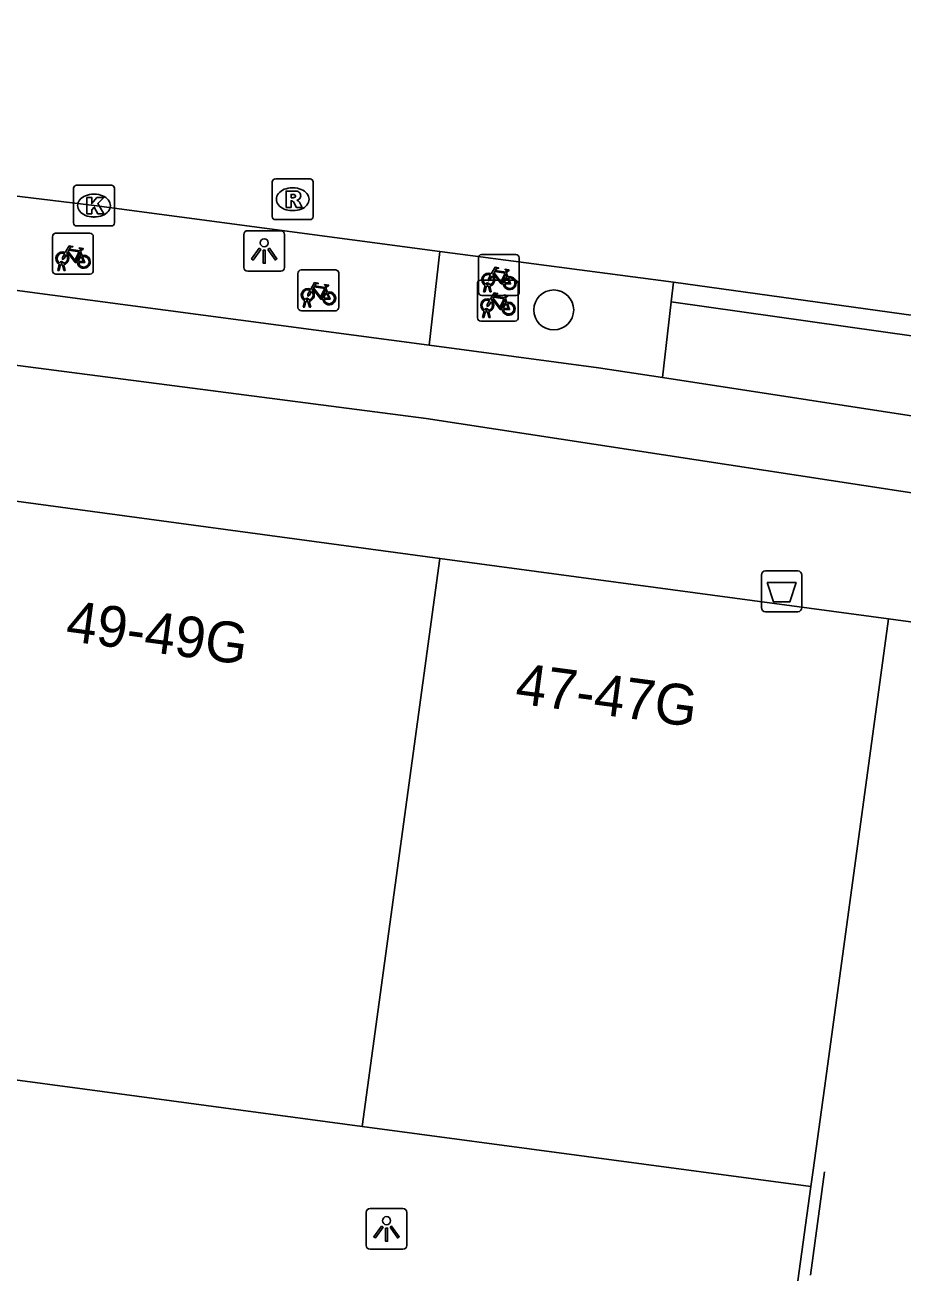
# Model space of a CAD drawing. Extents: x 160664 to 161506, y 382245 to 383288.
# Drawn here: x 160817.07 to 160838.59, y 383245.11 to 383275.84 of the extents above; entities that cross this region are included whole.
import ezdxf

# ---------------------------------------------------------------- set-up
doc = ezdxf.new("R2010")
doc.units = 0
for name, color, linetype in [('IMGEO_Afvalbak', 7, 'Continuous'), ('IMGEO_Berm_open', 7, 'Continuous'), ('IMGEO_Boom', 7, 'Continuous'), ('IMGEO_Fietsenrek', 7, 'Continuous'), ('IMGEO_Fietspad_gesloten', 7, 'Continuous'), ('IMGEO_Kolk', 7, 'Continuous'), ('IMGEO_Lichtpunt', 7, 'Continuous'), ('IMGEO_Muur', 7, 'Continuous'), ('IMGEO_Pand', 7, 'Continuous'), ('IMGEO_Pand_nummerreeks', 7, 'Continuous'), ('IMGEO_Rijbaan_lokaal_gesloten', 7, 'Continuous'), ('IMGEO_Rioolput', 7, 'Continuous'), ('IMGEO_Voetpad_open', 7, 'Continuous')]:
    doc.layers.add(name, color=color, linetype=linetype)

msp = doc.modelspace()

# ---------------------------------------------------------------- linework, layer by layer
at = {"layer": 'IMGEO_Afvalbak'}
for p, q in [((160835.118, 383261.549), (160835.118, 383262.349)), ((160835.118, 383262.349), (160835.118, 383261.549)), ((160835.218, 383262.449), (160836.008, 383262.449)), ((160836.008, 383262.449), (160835.218, 383262.449)), ((160836.108, 383262.349), (160836.108, 383261.549)), ((160836.108, 383261.549), (160836.108, 383262.349)), ((160836.008, 383261.449), (160835.218, 383261.449)), ((160835.218, 383261.449), (160836.008, 383261.449))]:
    msp.add_line(p, q, dxfattribs=at)
msp.add_lwpolyline([(160835.261, 383262.163), (160835.965, 383262.163), (160835.816, 383261.693), (160835.41, 383261.693), (160835.261, 383262.163)], dxfattribs=at)
for centre, start, end in [((160835.218, 383262.349), 90, 180), ((160835.218, 383262.349), 90, 180), ((160836.008, 383262.349), 0, 90), ((160836.008, 383262.349), 360, 90), ((160835.218, 383261.549), 180, 270), ((160835.218, 383261.549), 180, 270), ((160836.008, 383261.549), 270, 0), ((160836.008, 383261.549), 270, 0)]:
    msp.add_arc(centre, 0.1, start, end, dxfattribs=at)
at = {"layer": 'IMGEO_Berm_open'}
for points in [[(160827.23, 383270.288), (160826.971, 383267.984)], [(160832.69, 383267.191), (160832.907, 383269.052)]]:
    msp.add_lwpolyline(points, dxfattribs=at)
at = {"layer": 'IMGEO_Boom'}
msp.add_circle((160830.026, 383268.851), 0.489, dxfattribs=at)
at = {"layer": 'IMGEO_Fietsenrek'}
for p, q in [((160817.739, 383269.806), (160817.739, 383270.647)), ((160817.739, 383270.647), (160817.739, 383269.806)), ((160817.814, 383270.731), (160818.655, 383270.731)), ((160818.655, 383270.731), (160817.814, 383270.731)), ((160818.739, 383270.656), (160818.739, 383269.815)), ((160818.739, 383269.815), (160818.739, 383270.656)), ((160818.426, 383270.28), (160818.462, 383270.185)), ((160828.18, 383269.282), (160828.18, 383270.123)), ((160828.18, 383270.123), (160828.18, 383269.282)), ((160828.255, 383270.207), (160829.096, 383270.207)), ((160829.096, 383270.207), (160828.255, 383270.207)), ((160829.18, 383270.132), (160829.18, 383269.291)), ((160829.18, 383269.291), (160829.18, 383270.132)), ((160818.664, 383269.731), (160817.823, 383269.731)), ((160817.823, 383269.731), (160818.664, 383269.731)), ((160817.866, 383269.815), (160817.905, 383269.975)), ((160817.9, 383269.815), (160817.866, 383269.815)), ((160817.935, 383269.963), (160817.9, 383269.815)), ((160817.977, 383269.987), (160817.976, 383269.991)), ((160818.018, 383269.815), (160817.984, 383269.957)), ((160818.008, 383269.998), (160818.009, 383269.991)), ((160818.016, 383269.961), (160818.051, 383269.815)), ((160818.051, 383269.815), (160818.018, 383269.815)), ((160823.756, 383268.907), (160823.756, 383269.748)), ((160823.756, 383269.748), (160823.756, 383268.907)), ((160823.831, 383269.832), (160824.672, 383269.832)), ((160824.672, 383269.832), (160823.831, 383269.832)), ((160824.756, 383269.757), (160824.756, 383268.916)), ((160824.756, 383268.916), (160824.756, 383269.757)), ((160828.867, 383269.756), (160828.903, 383269.661)), ((160828.155, 383268.654), (160828.155, 383269.495)), ((160828.155, 383269.495), (160828.155, 383268.654)), ((160828.23, 383269.579), (160829.071, 383269.579)), ((160829.071, 383269.579), (160828.23, 383269.579)), ((160828.307, 383269.291), (160828.346, 383269.451)), ((160828.376, 383269.439), (160828.341, 383269.291)), ((160828.418, 383269.463), (160828.417, 383269.467)), ((160828.459, 383269.291), (160828.425, 383269.433)), ((160828.449, 383269.474), (160828.45, 383269.467)), ((160828.457, 383269.437), (160828.492, 383269.291)), ((160829.155, 383269.504), (160829.155, 383268.663)), ((160829.155, 383268.663), (160829.155, 383269.504)), ((160823.994, 383269.088), (160823.993, 383269.092)), ((160824.025, 383269.099), (160824.026, 383269.092)), ((160824.443, 383269.381), (160824.479, 383269.286)), ((160829.105, 383269.207), (160828.264, 383269.207)), ((160828.264, 383269.207), (160829.105, 383269.207)), ((160828.341, 383269.291), (160828.307, 383269.291)), ((160828.492, 383269.291), (160828.459, 383269.291)), ((160828.842, 383269.128), (160828.878, 383269.033)), ((160824.681, 383268.832), (160823.84, 383268.832)), ((160823.84, 383268.832), (160824.681, 383268.832)), ((160823.883, 383268.916), (160823.922, 383269.076)), ((160823.917, 383268.916), (160823.883, 383268.916)), ((160823.952, 383269.064), (160823.917, 383268.916)), ((160824.035, 383268.916), (160824.001, 383269.058)), ((160824.033, 383269.062), (160824.068, 383268.916)), ((160824.068, 383268.916), (160824.035, 383268.916)), ((160828.282, 383268.663), (160828.321, 383268.823)), ((160828.351, 383268.811), (160828.316, 383268.663)), ((160828.393, 383268.835), (160828.392, 383268.839)), ((160828.434, 383268.663), (160828.4, 383268.805)), ((160828.424, 383268.846), (160828.425, 383268.839)), ((160828.432, 383268.809), (160828.467, 383268.663)), ((160829.08, 383268.579), (160828.239, 383268.579)), ((160828.239, 383268.579), (160829.08, 383268.579)), ((160828.316, 383268.663), (160828.282, 383268.663)), ((160828.467, 383268.663), (160828.434, 383268.663))]:
    msp.add_line(p, q, dxfattribs=at)
for points in [[(160818.052, 383270.257), (160818.147, 383270.421), (160818.233, 383270.407), (160818.235, 383270.398), (160818.179, 383270.387), (160818.152, 383270.342), (160818.408, 383270.301)], [(160818.395, 383270.276), (160818.138, 383270.317), (160818.121, 383270.288), (160818.288, 383270.068), (160818.395, 383270.276)], [(160818.408, 383270.301), (160818.433, 383270.35), (160818.427, 383270.354), (160818.404, 383270.358), (160818.392, 383270.365), (160818.391, 383270.368), (160818.393, 383270.373), (160818.488, 383270.358), (160818.49, 383270.348), (160818.48, 383270.335), (160818.468, 383270.329), (160818.454, 383270.335), (160818.426, 383270.28)], [(160818.073, 383270.205), (160818.021, 383270.115), (160817.981, 383270.09), (160817.982, 383270.137), (160818.037, 383270.231)], [(160818.348, 383270.013), (160818.298, 383270.013), (160818.107, 383270.264), (160818.088, 383270.232)], [(160818.443, 383270.178), (160818.413, 383270.255), (160818.304, 383270.037), (160818.347, 383270.037)], [(160818.377, 383270.037), (160818.497, 383270.036), (160818.453, 383270.15)], [(160818.473, 383270.157), (160818.528, 383270.012), (160818.378, 383270.012)], [(160828.514, 383269.681), (160828.462, 383269.591), (160828.422, 383269.566), (160828.423, 383269.613), (160828.478, 383269.707)], [(160828.493, 383269.733), (160828.588, 383269.897), (160828.674, 383269.883), (160828.676, 383269.874), (160828.62, 383269.863), (160828.593, 383269.818), (160828.849, 383269.777)], [(160828.789, 383269.489), (160828.739, 383269.489), (160828.548, 383269.74), (160828.529, 383269.708)], [(160828.836, 383269.752), (160828.579, 383269.793), (160828.562, 383269.764), (160828.729, 383269.544), (160828.836, 383269.752)], [(160828.884, 383269.654), (160828.854, 383269.731), (160828.745, 383269.513), (160828.788, 383269.513)], [(160828.849, 383269.777), (160828.874, 383269.826), (160828.868, 383269.83), (160828.845, 383269.834), (160828.833, 383269.841), (160828.832, 383269.844), (160828.834, 383269.849), (160828.929, 383269.834), (160828.931, 383269.824), (160828.921, 383269.811), (160828.909, 383269.805), (160828.895, 383269.811), (160828.867, 383269.756)], [(160824.069, 383269.358), (160824.164, 383269.522), (160824.25, 383269.508), (160824.252, 383269.499), (160824.196, 383269.488), (160824.169, 383269.443), (160824.425, 383269.402)], [(160824.412, 383269.377), (160824.155, 383269.418), (160824.138, 383269.389), (160824.305, 383269.169), (160824.412, 383269.377)], [(160824.425, 383269.402), (160824.45, 383269.451), (160824.444, 383269.455), (160824.421, 383269.459), (160824.409, 383269.466), (160824.408, 383269.469), (160824.41, 383269.474), (160824.505, 383269.459), (160824.507, 383269.449), (160824.497, 383269.436), (160824.485, 383269.43), (160824.471, 383269.436), (160824.443, 383269.381)], [(160828.818, 383269.513), (160828.938, 383269.512), (160828.894, 383269.626)], [(160828.914, 383269.633), (160828.969, 383269.488), (160828.819, 383269.488)], [(160824.09, 383269.306), (160824.038, 383269.216), (160823.998, 383269.191), (160823.999, 383269.238), (160824.054, 383269.332)], [(160824.365, 383269.114), (160824.315, 383269.114), (160824.124, 383269.365), (160824.105, 383269.333)], [(160824.46, 383269.279), (160824.43, 383269.356), (160824.321, 383269.138), (160824.364, 383269.138)], [(160824.394, 383269.138), (160824.514, 383269.137), (160824.47, 383269.251)], [(160824.49, 383269.258), (160824.545, 383269.113), (160824.395, 383269.113)], [(160828.468, 383269.105), (160828.563, 383269.269), (160828.649, 383269.255), (160828.651, 383269.246), (160828.595, 383269.235), (160828.568, 383269.19), (160828.824, 383269.149)], [(160828.764, 383268.861), (160828.714, 383268.861), (160828.523, 383269.112), (160828.504, 383269.08)], [(160828.811, 383269.124), (160828.554, 383269.165), (160828.537, 383269.136), (160828.704, 383268.916), (160828.811, 383269.124)], [(160828.859, 383269.026), (160828.829, 383269.103), (160828.72, 383268.885), (160828.763, 383268.885)], [(160828.824, 383269.149), (160828.849, 383269.198), (160828.843, 383269.202), (160828.82, 383269.206), (160828.808, 383269.213), (160828.807, 383269.216), (160828.809, 383269.221), (160828.904, 383269.206), (160828.906, 383269.196), (160828.896, 383269.183), (160828.884, 383269.177), (160828.87, 383269.183), (160828.842, 383269.128)], [(160828.489, 383269.053), (160828.437, 383268.963), (160828.397, 383268.938), (160828.398, 383268.985), (160828.453, 383269.079)], [(160828.793, 383268.885), (160828.913, 383268.884), (160828.869, 383268.998)], [(160828.889, 383269.005), (160828.944, 383268.86), (160828.794, 383268.86)]]:
    msp.add_lwpolyline(points, dxfattribs=at)
for centre, radius, start, end in [((160817.817, 383270.653), 0.0779, 92.4484, 184.2845), ((160817.817, 383270.653), 0.0779, 92.4484, 184.2845), ((160818.661, 383270.653), 0.0779, 2.4484, 94.2845), ((160818.661, 383270.653), 0.0779, 2.4484, 94.2845), ((160817.979, 383270.116), 0.159, 62.6766, 242.1369), ((160817.979, 383270.116), 0.129, 63.3192, 238.903), ((160817.959, 383269.987), 0.0499, 12.8025, 158.6934), ((160817.959, 383269.987), 0.0174, 12.8025, 163.4502), ((160817.979, 383270.116), 0.129, 283.6043, 43.4302), ((160817.979, 383270.116), 0.159, 283.5766, 46.6042), ((160818.506, 383270.032), 0.159, 113.3408, 178.3217), ((160818.506, 383270.032), 0.159, 187.0065, 105.7708), ((160818.506, 383270.032), 0.129, 113.923, 177.9556), ((160818.506, 383270.032), 0.129, 188.6715, 104.5883), ((160828.258, 383270.129), 0.0779, 92.4484, 184.2845), ((160828.258, 383270.129), 0.0779, 92.4484, 184.2845), ((160829.102, 383270.129), 0.0779, 2.4484, 94.2845), ((160829.102, 383270.129), 0.0779, 2.4484, 94.2845), ((160817.817, 383269.809), 0.0779, 182.4484, 274.2845), ((160817.817, 383269.809), 0.0779, 182.4484, 274.2845), ((160817.979, 383270.116), 0.159, 253.9967, 271.7867), ((160817.979, 383270.116), 0.129, 253.415, 269.0204), ((160818.661, 383269.809), 0.0779, 272.4484, 4.2845), ((160818.661, 383269.809), 0.0779, 272.4484, 4.2845), ((160823.834, 383269.754), 0.0779, 92.4484, 184.2845), ((160823.834, 383269.754), 0.0779, 92.4484, 184.2845), ((160824.678, 383269.754), 0.0779, 2.4484, 94.2845), ((160824.678, 383269.754), 0.0779, 2.4484, 94.2845), ((160828.42, 383269.592), 0.159, 62.6766, 242.1369), ((160828.42, 383269.592), 0.129, 63.3192, 238.903), ((160828.42, 383269.592), 0.159, 283.5766, 46.6042), ((160828.233, 383269.501), 0.0779, 92.4484, 184.2845), ((160828.233, 383269.501), 0.0779, 92.4484, 184.2845), ((160828.4, 383269.463), 0.0499, 12.8025, 158.6934), ((160828.42, 383269.592), 0.159, 253.9967, 271.7867), ((160828.4, 383269.463), 0.0174, 12.8025, 163.4502), ((160828.42, 383269.592), 0.129, 253.415, 269.0204), ((160828.42, 383269.592), 0.129, 283.6043, 43.4302), ((160828.947, 383269.508), 0.159, 113.3408, 178.3217), ((160828.947, 383269.508), 0.159, 187.0065, 105.7708), ((160828.947, 383269.508), 0.129, 113.923, 177.9556), ((160828.947, 383269.508), 0.129, 188.6715, 104.5883), ((160829.077, 383269.501), 0.0779, 2.4484, 94.2845), ((160829.077, 383269.501), 0.0779, 2.4484, 94.2845), ((160823.996, 383269.217), 0.159, 62.6766, 242.1369), ((160823.996, 383269.217), 0.129, 63.3192, 238.903), ((160823.976, 383269.088), 0.0499, 12.8025, 158.6934), ((160823.976, 383269.088), 0.0174, 12.8025, 163.4502), ((160823.996, 383269.217), 0.129, 253.415, 269.0204), ((160823.996, 383269.217), 0.129, 283.6043, 43.4302), ((160823.996, 383269.217), 0.159, 283.5766, 46.6042), ((160824.523, 383269.133), 0.159, 113.3408, 178.3217), ((160824.523, 383269.133), 0.159, 187.0065, 105.7708), ((160824.523, 383269.133), 0.129, 113.923, 177.9556), ((160824.523, 383269.133), 0.129, 188.6715, 104.5883), ((160828.258, 383269.285), 0.0779, 182.4484, 274.2845), ((160828.258, 383269.285), 0.0779, 182.4484, 274.2845), ((160828.395, 383268.964), 0.159, 62.6766, 242.1369), ((160828.395, 383268.964), 0.129, 63.3192, 238.903), ((160828.395, 383268.964), 0.159, 283.5766, 46.6042), ((160829.102, 383269.285), 0.0779, 272.4484, 4.2845), ((160829.102, 383269.285), 0.0779, 272.4484, 4.2845), ((160823.834, 383268.91), 0.0779, 182.4484, 274.2845), ((160823.834, 383268.91), 0.0779, 182.4484, 274.2845), ((160823.996, 383269.217), 0.159, 253.9967, 271.7867), ((160824.678, 383268.91), 0.0779, 272.4484, 4.2845), ((160824.678, 383268.91), 0.0779, 272.4484, 4.2845), ((160828.375, 383268.835), 0.0499, 12.8025, 158.6934), ((160828.395, 383268.964), 0.159, 253.9967, 271.7867), ((160828.375, 383268.835), 0.0174, 12.8025, 163.4502), ((160828.395, 383268.964), 0.129, 253.415, 269.0204), ((160828.395, 383268.964), 0.129, 283.6043, 43.4302), ((160828.922, 383268.88), 0.159, 113.3408, 178.3217), ((160828.922, 383268.88), 0.159, 187.0065, 105.7708), ((160828.922, 383268.88), 0.129, 113.923, 177.9556), ((160828.922, 383268.88), 0.129, 188.6715, 104.5883), ((160828.233, 383268.657), 0.0779, 182.4484, 274.2845), ((160828.233, 383268.657), 0.0779, 182.4484, 274.2845), ((160829.077, 383268.657), 0.0779, 272.4484, 4.2845), ((160829.077, 383268.657), 0.0779, 272.4484, 4.2845)]:
    msp.add_arc(centre, radius, start, end, dxfattribs=at)
at = {"layer": 'IMGEO_Fietspad_gesloten'}
for points in [[(160749.571, 383275.838), (160772.375, 383273.271), (160826.897, 383266.189), (160865.807, 383260.226)], [(160826.971, 383267.984), (160814.961, 383269.581)], [(160832.69, 383267.191), (160831.127, 383267.431), (160826.971, 383267.984)], [(160850.573, 383264.439), (160832.69, 383267.191)]]:
    msp.add_lwpolyline(points, dxfattribs=at)
at = {"layer": 'IMGEO_Kolk'}
for p, q in [((160818.33, 383271.91), (160819.182, 383271.91)), ((160818.255, 383270.984), (160818.255, 383271.836)), ((160818.743, 383271.69), (160818.768, 383271.69)), ((160819.256, 383271.836), (160819.256, 383270.984)), ((160818.766, 383271.13), (160818.741, 383271.13)), ((160819.182, 383270.91), (160818.33, 383270.91))]:
    msp.add_line(p, q, dxfattribs=at)
for points in [[(160818.33, 383271.91), (160819.182, 383271.91)], [(160818.255, 383270.984), (160818.255, 383271.836)], [(160818.576, 383271.61), (160818.699, 383271.61), (160818.699, 383271.459), (160818.829, 383271.61), (160818.993, 383271.61), (160818.847, 383271.459), (160819, 383271.21), (160818.848, 383271.21), (160818.763, 383271.374), (160818.699, 383271.307), (160818.699, 383271.21), (160818.576, 383271.21), (160818.576, 383271.61)], [(160819.256, 383271.836), (160819.256, 383270.984)], [(160819.182, 383270.91), (160818.33, 383270.91)]]:
    msp.add_lwpolyline(points, dxfattribs=at)
for centre, start, end in [((160818.332, 383271.834), 91.552, 178.448), ((160818.332, 383271.834), 91.552, 178.448), ((160819.18, 383271.834), 1.552, 88.448), ((160819.18, 383271.834), 1.552, 88.448), ((160818.332, 383270.986), 181.552, 268.448), ((160818.332, 383270.986), 181.552, 268.448), ((160819.18, 383270.986), 271.552, 358.448), ((160819.18, 383270.986), 271.552, 358.448)]:
    msp.add_arc(centre, 0.0765, start, end, dxfattribs=at)
for centre, major_axis, ratio, start_param, end_param in [((160818.742, 383271.41), (-0.387, 0.002), 0.722429, 4.712389, 7.853982), ((160818.767, 383271.41), (-0.39, 0.002), 0.717154, 1.570796, 4.712389)]:
    msp.add_ellipse(centre, major_axis=major_axis, ratio=ratio, start_param=start_param, end_param=end_param, dxfattribs=at)
at = {"layer": 'IMGEO_Lichtpunt'}
for p, q in [((160822.43, 383270.7), (160822.43, 383269.893)), ((160822.43, 383270.7), (160822.43, 383269.893)), ((160823.332, 383270.795), (160822.524, 383270.795)), ((160823.332, 383270.795), (160822.524, 383270.795)), ((160823.426, 383269.893), (160823.426, 383270.7)), ((160823.426, 383269.893), (160823.426, 383270.7)), ((160822.524, 383269.799), (160823.332, 383269.799)), ((160822.524, 383269.799), (160823.332, 383269.799)), ((160825.428, 383246.715), (160825.428, 383245.908)), ((160825.428, 383246.715), (160825.428, 383245.908)), ((160826.33, 383246.81), (160825.522, 383246.81)), ((160826.33, 383246.81), (160825.522, 383246.81)), ((160826.424, 383245.908), (160826.424, 383246.715)), ((160826.424, 383245.908), (160826.424, 383246.715)), ((160825.522, 383245.814), (160826.33, 383245.814)), ((160825.522, 383245.814), (160826.33, 383245.814))]:
    msp.add_line(p, q, dxfattribs=at)
for points in [[(160822.804, 383270.364), (160822.843, 383270.336), (160822.655, 383270.074), (160822.617, 383270.101), (160822.804, 383270.364)], [(160822.906, 383270.316), (160822.953, 383270.316), (160822.953, 383269.994), (160822.906, 383269.994), (160822.906, 383270.316)], [(160823.016, 383270.336), (160823.054, 383270.363), (160823.241, 383270.101), (160823.202, 383270.073), (160823.016, 383270.336)], [(160825.802, 383246.379), (160825.841, 383246.351), (160825.653, 383246.089), (160825.615, 383246.116), (160825.802, 383246.379)], [(160826.014, 383246.351), (160826.052, 383246.378), (160826.239, 383246.116), (160826.2, 383246.088), (160826.014, 383246.351)], [(160825.904, 383246.331), (160825.951, 383246.331), (160825.951, 383246.009), (160825.904, 383246.009), (160825.904, 383246.331)]]:
    msp.add_lwpolyline(points, dxfattribs=at)
for centre in [(160822.929, 383270.498), (160825.927, 383246.513)]:
    msp.add_circle(centre, 0.0994, dxfattribs=at)
for centre, start, end in [((160822.524, 383270.7), 90, 180), ((160822.524, 383270.7), 90, 180), ((160823.332, 383270.7), 0, 90), ((160823.332, 383270.7), 0, 90), ((160822.524, 383269.893), 180, 270), ((160822.524, 383269.893), 180, 270), ((160823.332, 383269.893), 270, 0), ((160823.332, 383269.893), 270, 360), ((160825.522, 383246.715), 90, 180), ((160825.522, 383246.715), 90, 180), ((160826.33, 383246.715), 0, 90), ((160826.33, 383246.715), 0, 90), ((160825.522, 383245.908), 180, 270), ((160825.522, 383245.908), 180, 270), ((160826.33, 383245.908), 270, 0), ((160826.33, 383245.908), 270, 360)]:
    msp.add_arc(centre, 0.0946, start, end, dxfattribs=at)
at = {"layer": 'IMGEO_Muur'}
msp.add_lwpolyline([(160836.319, 383245.176), (160836.664, 383247.71)], dxfattribs=at)
at = {"layer": 'IMGEO_Pand'}
for points in [[(160816.231, 383264.24), (160827.231, 383262.757)], [(160825.326, 383248.825), (160827.231, 383262.757)], [(160827.231, 383262.757), (160838.231, 383261.273)], [(160838.231, 383261.273), (160836.696, 383250), (160836.383, 383247.748), (160836.327, 383247.348)], [(160838.231, 383261.273), (160844.135, 383260.477)], [(160825.326, 383248.825), (160818.534, 383249.737), (160816.578, 383250), (160814.324, 383250.303)], [(160836.327, 383247.348), (160825.326, 383248.825)], [(160836.012, 383245.041), (160836.327, 383247.348)]]:
    msp.add_lwpolyline(points, dxfattribs=at)
at = {"layer": 'IMGEO_Rijbaan_lokaal_gesloten'}
for points in [[(160815.172, 383271.845), (160818.756, 383271.41), (160827.23, 383270.288)], [(160827.23, 383270.288), (160832.959, 383269.529)], [(160832.959, 383269.529), (160844.144, 383267.979)]]:
    msp.add_lwpolyline(points, dxfattribs=at)
at = {"layer": 'IMGEO_Rioolput'}
for p, q in [((160823.126, 383271.14), (160823.126, 383271.992)), ((160823.201, 383272.066), (160824.053, 383272.066)), ((160823.614, 383271.846), (160823.639, 383271.846)), ((160824.127, 383271.992), (160824.127, 383271.14)), ((160823.637, 383271.286), (160823.612, 383271.286)), ((160824.053, 383271.066), (160823.201, 383271.066))]:
    msp.add_line(p, q, dxfattribs=at)
for points in [[(160823.126, 383271.14), (160823.126, 383271.992)], [(160823.201, 383272.066), (160824.053, 383272.066)], [(160824.127, 383271.992), (160824.127, 383271.14)], [(160823.715, 383271.764), (160823.463, 383271.766), (160823.463, 383271.366)], [(160823.641, 383271.685), (160823.587, 383271.685), (160823.587, 383271.604)], [(160823.587, 383271.604), (160823.639, 383271.604)], [(160823.463, 383271.366), (160823.587, 383271.366), (160823.587, 383271.528), (160823.598, 383271.528)], [(160823.645, 383271.499), (160823.716, 383271.366), (160823.856, 383271.366), (160823.791, 383271.492)], [(160824.053, 383271.066), (160823.201, 383271.066)]]:
    msp.add_lwpolyline(points, dxfattribs=at)
for centre, radius, start, end in [((160823.203, 383271.99), 0.0765, 91.552, 178.448), ((160823.203, 383271.99), 0.0765, 91.552, 178.448), ((160824.051, 383271.99), 0.0765, 1.552, 88.448), ((160824.051, 383271.99), 0.0765, 1.552, 88.448), ((160823.623, 383271.793), 0.19, 274.7715, 282.9687), ((160823.647, 383271.589), 0.0964, 77.0061, 93.1865), ((160823.661, 383271.646), 0.0378, 276.6634, 79.6772), ((160823.714, 383271.654), 0.109, 350.3612, 89.416), ((160823.712, 383271.654), 0.112, 277.5842, 350.9817), ((160823.696, 383271.439), 0.108, 29.5134, 73.7905), ((160823.597, 383271.475), 0.0533, 26.0293, 88.6989), ((160823.203, 383271.142), 0.0765, 181.552, 268.448), ((160823.203, 383271.142), 0.0765, 181.552, 268.448), ((160824.051, 383271.142), 0.0765, 271.552, 358.448), ((160824.051, 383271.142), 0.0765, 271.552, 358.448)]:
    msp.add_arc(centre, radius, start, end, dxfattribs=at)
for centre, major_axis, ratio, start_param, end_param in [((160823.613, 383271.566), (-0.387, 0.002), 0.722429, 4.712389, 7.853982), ((160823.638, 383271.566), (-0.39, 0.002), 0.717154, 1.570796, 4.712389)]:
    msp.add_ellipse(centre, major_axis=major_axis, ratio=ratio, start_param=start_param, end_param=end_param, dxfattribs=at)
at = {"layer": 'IMGEO_Voetpad_open'}
for points in [[(160832.907, 383269.052), (160832.959, 383269.529)], [(160844.144, 383267.979), (160844.049, 383267.473), (160832.907, 383269.052)]]:
    msp.add_lwpolyline(points, dxfattribs=at)

# ---------------------------------------------------------------- texts
at = {"layer": 'IMGEO_Pand_nummerreeks'}
for s, rotation, p in [('49-49G', 352.3332, (160818.036, 383260.74)), ('47-47G', 352.4215, (160829.054, 383259.206))]:
    msp.add_text(s, height=1, rotation=rotation, dxfattribs=at).set_placement(p)

doc.saveas('drawing.dxf')
